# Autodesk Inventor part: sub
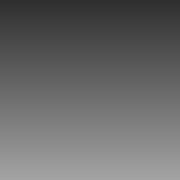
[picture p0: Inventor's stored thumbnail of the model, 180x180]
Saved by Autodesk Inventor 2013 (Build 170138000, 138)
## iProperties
Created: 2009-11
Part Number: sub
Document SubType Name: Modeling
Designer: pokornp
Density: 1 g/cm^3
Material: Generic
Author: pokornp
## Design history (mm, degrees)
sketch "Sketch1"
  geometry: L1 (0, 0)-(10000, 0); L2 (0, -1940)-(10000, -1940)
  constraints: 4 end point, 2 vertical alignment, 1 horizontal, 1 parallel
  dimensions: "d0" = 10000 dimension on L1.start L1.end L1 L2.start L2.end L2; "d0" = 10000 distance of L2.start L2.end; "d1" = 1940 distance between parallel lines of L2 L1
